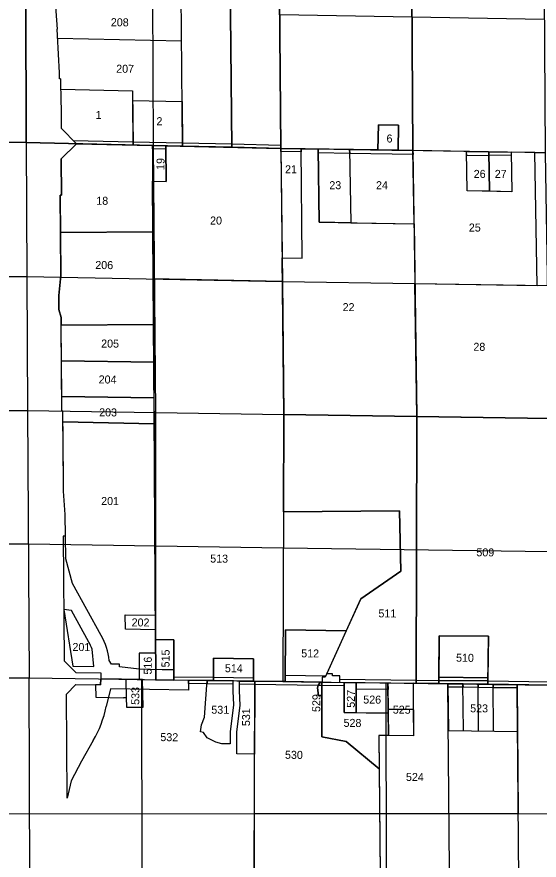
# Model space of a CAD drawing. Extents: x 582596 to 627039, y 145946 to 197316.
# Drawn here: x 594033 to 599237, y 163252 to 171651 of the extents above; entities that cross this region are included whole.
import ezdxf

# ---------------------------------------------------------------- set-up
doc = ezdxf.new("R2010")
doc.units = 0
for name, color, linetype in [('Defpoints 2', 7, 'Continuous'), ('E_RW_Existing', 7, 'Continuous'), ('E_RW_SixteenthLine', 7, 'Continuous'), ('P_RW_PropertyLine', 7, 'Continuous'), ('P_RW_QuarterLine', 7, 'Continuous'), ('P_RW_SectionLine', 7, 'Continuous')]:
    doc.layers.add(name, color=color, linetype=linetype)

msp = doc.modelspace()

# ---------------------------------------------------------------- linework, layer by layer
at = {"layer": 'Defpoints'}
msp.add_line((594439.8, 171440.4), (595673.8, 171412.6), dxfattribs=at)
msp.add_lwpolyline([(595191.7, 170375), (595187.7, 170818.2), (595679.3, 170807.1), (595683.3, 170363.9), (595191.7, 170375)], dxfattribs=at)
at = {"layer": 'E_RW_Existing'}
for p, q in [((594397.8, 172047.5), (594434, 171527.1)), ((594474.4, 168571.6), (594474.3, 168580.4)), ((594481.1, 167725.8), (594474.4, 168571.6)), ((594491.1, 167725.6), (594481.1, 167725.8)), ((594493.4, 167426.7), (594491.1, 167725.6)), ((594496.6, 167026.7), (594493.4, 167426.7)), ((594497.4, 166926.7), (594496.6, 167026.7)), ((594513.3, 166695.2), (594497.4, 166926.7)), ((594517.2, 166478.1), (594513.3, 166695.2)), ((594517.2, 166478.1), (594495, 166478.6)), ((594495, 166478.6), (594504.9, 165237)), ((594521.3, 166252.8), (594517.2, 166478.1)), ((594588.3, 166008.9), (594521.3, 166252.8)), ((594873.9, 165490.7), (594588.3, 166008.9)), ((594504.9, 165237), (594620.7, 165120.3)), ((594975, 165205.1), (594953.1, 165240.7)), ((595057.5, 165203.9), (594975, 165205.1)), ((595057.1, 165176.9), (595057.5, 165203.9)), ((595253.2, 165154), (595057.1, 165176.9)), ((595481.3, 165147.7), (595253.2, 165154)), ((595598.3, 165146), (595481.3, 165147.7)), ((595598.3, 165046), (595598.3, 165146)), ((594620.7, 165120.3), (594869.6, 165116.7)), ((594868.2, 165056.7), (595598.3, 165046)), ((594869.6, 165116.7), (594868.7, 165056.7))]:
    msp.add_line(p, q, dxfattribs=at)
for points in [[(594595.4, 170421.5), (595191.4, 170408), (595191.7, 170375), (594628.7, 170387.7)], [(595191.4, 170408), (595683, 170396.9), (595683.3, 170363.9), (595191.7, 170375)], [(595518.5, 170367.6), (595518.7, 170334.6), (595383.7, 170337.7), (595383.5, 170370.7)], [(596173.7, 170385.9), (596174, 170352.8), (595683.3, 170363.9), (595683, 170396.9)], [(596664.4, 170341.8), (596174, 170352.8), (596173.7, 170385.9), (596664.1, 170374.8)], [(596864.4, 170338.4), (596864.8, 170305.4), (596664.8, 170308.8), (596664.4, 170341.8)], [(597033.7, 170335.6), (597349.1, 170330.3), (597349.7, 170290.3), (597034.2, 170295.6)], [(597349.7, 170290.3), (597349.1, 170330.3), (597980, 170319.8), (597980.6, 170279.8)], [(598514.6, 170310.8), (598736, 170307.1), (598736.7, 170267.1), (598515.3, 170270.8)], [(598736, 170307.1), (598957.4, 170303.4), (598958, 170270.4), (598736.6, 170274.1)], [(595991.5, 165073.2), (595991.4, 165040.2), (595598.3, 165046), (595598.3, 165079)], [(595742.8, 165010.9), (595742.4, 165043.9), (595930.5, 165041.1), (595928.1, 165008.2)], [(596391.3, 165034.4), (595991.4, 165040.2), (595991.5, 165073.2), (596391.4, 165067.4)], [(596708.2, 165094.8), (597111.7, 165089.5), (597105, 165074.6), (597076.4, 165075), (597075.7, 165025), (596707.9, 165029.8)], [(597250.6, 165022.7), (597251.1, 165055.7), (598011.3, 165045.9), (598011.2, 165012.9)], [(598236.5, 165042.9), (598236.1, 165010), (598011.2, 165012.9), (598011.3, 165045.9)], [(598726.5, 165036.6), (598726.1, 165003.6), (598236.1, 165010), (598236.5, 165042.9)], [(598726.9, 165068.6), (598726.5, 165036.6), (598236.5, 165042.9), (598237, 165074.9)], [(595930.5, 165041.1), (596186.7, 165037.4), (596186.6, 165004.4), (595928.1, 165008.2)], [(596404.6, 165034.2), (596404.6, 165001.2), (596252.6, 165003.4), (596252.7, 165036.4)], [(596404.6, 165001.2), (596404.6, 165034.2), (596681.8, 165030.1), (597056.7, 165025.3), (597035.1, 164992.5)], [(597072.8, 165025), (597072.8, 164992), (597035.1, 164992.5), (597056.7, 165025.3)], [(597295.6, 165022.2), (597295.5, 164989.2), (597072.8, 164992), (597072.8, 165025)], [(597413.2, 164955.6), (597413.4, 165020.6), (597730.7, 165016.5), (597731.3, 164951.5)], [(598328.5, 164975.8), (598328.2, 165008.8), (598478.2, 165006.8), (598478.5, 164973.8)], [(598478.5, 164973.8), (598478.2, 165006.8), (598628.2, 165004.9), (598628.5, 164971.9)], [(598628.5, 164971.9), (598628.2, 165004.9), (598778.2, 165002.9), (598778.5, 164969.9)], [(599788.1, 165022.8), (599787.6, 164989.8), (599340.6, 164995.6), (598726.1, 165003.6), (598726.5, 165036.6), (599341.2, 165028.6)], [(598778.5, 164969.9), (598778.2, 165002.9), (599017.9, 164999.8), (599018.2, 164966.8)]]:
    msp.add_lwpolyline(points, close=True, dxfattribs=at)
msp.add_lwpolyline([(594794.5, 164442.2), (594676.6, 164237.3), (594574.6, 164043.6), (594535.8, 163868.7), (594527.5, 164906.8), (594621.6, 165000.3), (594867.9, 164996.7), (594868.8, 165056.7), (595742.4, 165043.9), (595743.8, 164945.8), (594964.9, 164957.3), (594924.3, 164781.8)], dxfattribs=at)
for centre, radius, start, end in [((594274.8, 165163.4), 682.7, 6.50215, 28.64904), ((593784.6, 165023), 1165, 330.10094, 348.05303)]:
    msp.add_arc(centre, radius, start, end, dxfattribs=at)
at = {"layer": 'E_RW_SixteenthLine'}
for p, q in [((595395.6, 170370.4), (595380.5, 173021.2)), ((597961, 172974.2), (597980, 170319.8)), ((599288.6, 171623.9), (596652.4, 171670.1)), ((595416.4, 167710.5), (595395.6, 170370.4)), ((597980, 170319.8), (598016.8, 167670.6)), ((591490.3, 169075.1), (594133.7, 169065.2)), ((594133.7, 169065.2), (596678.4, 169015.7)), ((596678.4, 169015.7), (599318.5, 168974.7)), ((595418.3, 165048.6), (595416.4, 167710.5)), ((598016.8, 167670.6), (598011.2, 165012.9)), ((594147.7, 166399.3), (591503.8, 166402.7)), ((596687.1, 166359.8), (594147.7, 166399.3)), ((599341, 166323.6), (596687.1, 166359.8)), ((595281.4, 162380), (595279.8, 165050.7)), ((597719.3, 162417.8), (597711.3, 165017)), ((591502, 163742), (594160.2, 163713)), ((594160.2, 163713), (596401, 163717.7)), ((596401, 163717.7), (599029.5, 163717.1)), ((599029.5, 163717.1), (601684.2, 163696.7))]:
    msp.add_line(p, q, dxfattribs=at)
at = {"layer": 'P_RW_PropertyLine'}
for p, q in [((594126.8, 170399), (594120.8, 173044)), ((594469.8, 171032.9), (594459.8, 171032.5)), ((594126.8, 170399), (596664.4, 170341.8)), ((594628.7, 170387.7), (594476.2, 170237.4)), ((595383.5, 170370.7), (595390, 170370.5)), ((595518.5, 170367.6), (595520.8, 170012)), ((596664.4, 170341.8), (596864.4, 170338.4)), ((599195.6, 170299.4), (599295.6, 170297.8)), ((594476.2, 170237.4), (594479, 169876.7)), ((595391, 170014.9), (595385.8, 170015)), ((595385.8, 170015), (595520.8, 170012)), ((594479, 169876.7), (594464, 169876.6)), ((594464, 169876.6), (594470.4, 169076.6)), ((594470.4, 169076.6), (594450.6, 168876.4)), ((594450.6, 168876.4), (594451.7, 168736.4)), ((594451.7, 168736.4), (594473.7, 168656.6)), ((594473.7, 168656.6), (594474.3, 168580.4)), ((594474.3, 168580.4), (595395, 168587.3)), ((595401.3, 167597.4), (595417.7, 165048.7)), ((594500.8, 165749.4), (594503, 165749.4)), ((595119.8, 165053), (595124, 164873.2)), ((595742.8, 165010.9), (595742.4, 165043.9)), ((598482.4, 164541.8), (598478.2, 165006.8)), ((598632.4, 164539.9), (598628.2, 165004.9)), ((598782.4, 164537.9), (598778.2, 165002.9))]:
    msp.add_line(p, q, dxfattribs=at)
for points in [[(596149.9, 173007.2), (596174, 170352.8), (595683.3, 170363.9), (595659.1, 173016.1), (596149.9, 173007.2)], [(596640.3, 172998.3), (596664.4, 170341.8), (596174, 170352.8), (596149.9, 173007.2), (596640.3, 172998.3)], [(594472.9, 170931.3), (595186.8, 170915.2), (595191.7, 170375), (594629, 170387.7)], [(594628.7, 170387.7), (594478.8, 170539.7), (594477.9, 170652.7)], [(597980, 170319.8), (597998.4, 168995.2), (599218.6, 168976.3), (599195.6, 170299.4), (598957.4, 170303.4), (598964.3, 169910.1), (598521.4, 169917.5), (598514.6, 170310.8), (597980, 170319.8)], [(596682, 165030.1), (596391.3, 165034.4), (596392.2, 165258.6), (595992.2, 165264.5), (595991.4, 165040.2), (595598.3, 165046), (595598, 165446), (595415.1, 165448.7), (595400.5, 167710.7), (595392.1, 169040.7), (596678.4, 169015.7), (596692.3, 167689.6), (596688.5, 166720.6), (597846.4, 166732.4), (597858.5, 166129.5), (597459.3, 165854.1), (597315.1, 165536.9), (596709.9, 165544.8), (596707.9, 165029.8), (596682, 165030.1)], [(594491.9, 167619.4), (595401.3, 167597.4), (595416, 165312.7), (595253.2, 165315.1), (595253.3, 165154), (595057.1, 165176.9), (595057.5, 165203.9), (594975, 165205.1), (594953.1, 165240.7)], [(594873.9, 165490.7), (594588.3, 166008.9), (594521.3, 166252.8), (594517.2, 166478.1), (594513.3, 166695.2), (594497.4, 166926.7), (594493.4, 167426.7), (594491.9, 167619.4)], [(594751.3, 165423.1), (594577.3, 165738.9), (594503, 165749.4), (594592.1, 165184.7), (594800.1, 165181.7)], [(594800.1, 165181.7), (594783.2, 165353.8)], [(596391.3, 165034.4), (595991.4, 165040.2), (595992.2, 165264.5), (596392.2, 165258.6), (596391.3, 165034.4)], [(596186.7, 165037.4), (596186.3, 164936.4), (596190.8, 164798.4), (596158.4, 164530.8), (596158, 164410.1), (596074.1, 164410.7), (596015.2, 164426.6), (595928.4, 164469.4), (595893.6, 164524.2), (595863.3, 164530.6), (595873.6, 164598.8), (595904.1, 164677.6), (595930.5, 165041.1), (596186.7, 165037.4)], [(597035.3, 164892.5), (597035.5, 164918.7), (597029.1, 164967.8), (597034.9, 164992.3), (597056.7, 165025.3)], [(597056.7, 165025.3), (597072.8, 165025), (597073, 164892), (597035.3, 164892.5)]]:
    msp.add_lwpolyline(points, dxfattribs=at)
for points in [[(596640.3, 172998.3), (597961, 172974.2), (597980, 170319.8), (597830.8, 170322.3), (597835, 170572.2), (597635, 170575.6), (597630.8, 170325.6), (596664.4, 170341.8)], [(597961, 172974.2), (599281.7, 172950), (599295.6, 170297.8), (597980, 170319.8)], [(597630.8, 170325.6), (597635, 170575.6), (597835, 170572.2), (597830.8, 170322.3)], [(594628.7, 170387.7), (595383.5, 170370.7), (595385.8, 170015), (595389.1, 169511.4), (594467, 169504.5), (594464, 169876.6), (594479, 169876.7), (594476.2, 170237.4)], [(596664.4, 170341.8), (596678.4, 169015.7), (595392.1, 169040.7), (595385.8, 170015), (595520.8, 170012), (595518.5, 170367.6)], [(597990.2, 169589.2), (598016.8, 167670.6), (596692.3, 167689.6), (596675.9, 169252.8), (596875.9, 169249.5), (596864.4, 170338.4), (597033.7, 170335.6), (597043.9, 169605)], [(597349.1, 170330.3), (597359.3, 169599.8), (597043.9, 169605), (597033.7, 170335.6)], [(597990.2, 169589.2), (597980, 170319.8), (597349.1, 170330.3), (597359.3, 169599.8)], [(599295.6, 170297.8), (599341.4, 167651.7), (598016.8, 167670.6), (597998.5, 168995.3), (599218.6, 168976.3), (599195.6, 170299.4)], [(598736, 170307.1), (598742.9, 169913.8), (598521.4, 169917.5), (598514.6, 170310.8)], [(598957.4, 170303.4), (598964.3, 169910.1), (598742.9, 169913.8), (598736, 170307.1)], [(594467, 169504.5), (595389.1, 169511.4), (595395, 168587.3), (594474.3, 168580.4), (594473.7, 168656.6), (594451.7, 168736.4), (594450.6, 168876.4), (594470.4, 169076.6)], [(594474.3, 168580.4), (595394.9, 168587.3), (595397.3, 168212.2), (594477.1, 168225.4)], [(594477.1, 168225.4), (595397.3, 168212.2), (595399.6, 167857.2), (594479.9, 167870.5)], [(594479.9, 167870.5), (595399.6, 167857.2), (595401.3, 167597.4), (594491.9, 167619.4), (594491.1, 167725.6), (594481.1, 167725.6)], [(596688.5, 166720.6), (596692.3, 167689.6), (598016.8, 167670.6), (598011.2, 165012.9), (597250.6, 165022.7), (597251.5, 165087.7), (597176.5, 165088.7), (597176.7, 165108.7), (597120.8, 165109.4), (597459.3, 165854.1), (597858.5, 166129.5), (597846.4, 166732.4)], [(599341.4, 167651.7), (600399.3, 167633), (600406.1, 164981.8), (600277.6, 164983.4), (600283.8, 165461.4), (599793.8, 165467.8), (599787.6, 164989.8), (599340.6, 164995.6), (598726.1, 165003.6), (598732.3, 165481.6), (598242.3, 165487.9), (598236.1, 165010), (598011.2, 165012.9), (598016.8, 167670.6)], [(599341.4, 167651.7), (599340.6, 164995.6), (598726.1, 165003.6), (598732.3, 165481.6), (598242.3, 165487.9), (598236.1, 165010), (598011.2, 165012.9), (598016.8, 167670.6)], [(595414.5, 165546.7), (595114.5, 165551.1), (595113.6, 165696.3), (595413.6, 165691.9)], [(596707.9, 165029.8), (596709.9, 165544.8), (597315.1, 165536.9), (597105, 165074.6), (597076.4, 165075), (597075.7, 165025)], [(598237, 165074.9), (598242.3, 165487.9), (598732.3, 165481.6), (598726.9, 165068.6)], [(595598.3, 165146), (595417.1, 165149.5), (595415.1, 165448.7), (595598, 165446)], [(595418.3, 165048.6), (595418.1, 165448.6), (595598, 165446), (595598.3, 165046)], [(595418.3, 165048.6), (595418.2, 165312.6), (595253.2, 165315.1), (595253.4, 165051.1)], [(594816.3, 164997.5), (594819.2, 164874.4), (595095.7, 164870.3), (595095.7, 164873.6), (595124, 164873.2), (595126.3, 164777.4), (595291.3, 164775), (595284.8, 165050.6), (594868.8, 165056.7), (594867.9, 164996.7)], [(596404.6, 165034.2), (596402.6, 164307.2), (596223.6, 164309.8), (596224.4, 164526.7), (596256.9, 164795.5), (596252.3, 164937.3), (596252.7, 165036.4)], [(597056.7, 165025.3), (597034.9, 164992.3), (597029.1, 164967.8), (597035.5, 164918.7), (597035.3, 164892.5), (597073, 164892), (597073.5, 164480.9), (597315.4, 164433.2), (597642.9, 164162), (597658.7, 162417.1), (596397.3, 162401.2), (596404.6, 165034.2), (596681.8, 165030.1)], [(597072.8, 165025), (597295.6, 165022.2), (597294.7, 164722.1), (597733.4, 164716.5), (597735.4, 164492.5), (597639.8, 164493.7), (597642.9, 164162), (597315.4, 164433.2), (597073.5, 164480.9)], [(597295.6, 165022.2), (597413.4, 165020.6), (597412.5, 164720.6), (597294.7, 164722.1)], [(597413.4, 165020.6), (597730.7, 165016.5), (597733.4, 164716.5), (597412.5, 164720.6)], [(598328.2, 165008.8), (597980.7, 165013.3), (597985.4, 164489.3), (597639.9, 164493.7), (597658.7, 162417.1), (598351.6, 162425.8)], [(597980.7, 165013.3), (597983.1, 164751.3), (597733.1, 164754.5), (597730.7, 165016.5)], [(599017.9, 164999.8), (598328.2, 165008.8), (598332.4, 164543.8), (599022.1, 164534.8)], [(599017.9, 164999.8), (599029.5, 163717.1), (600356.9, 163706.9), (600345.1, 164982.6), (599340.6, 164995.6)], [(597983.1, 164751.3), (597985.4, 164489.3), (597735.4, 164492.5), (597733.1, 164754.5)]]:
    msp.add_lwpolyline(points, close=True, dxfattribs=at)
for centre, radius, start, end in [((580243.9, 170539.9), 14224.5, 1.98477, 3.97988), ((580244.5, 170539.9), 14233.9, 0.45404, 1.98479), ((580244.5, 170539.9), 14233.9, 1.57576, 1.98479), ((580244.5, 170539.9), 14233.9, 0.45404, 1.57576), ((594274.8, 165163.4), 682.7, 6.50215, 28.64904), ((594287.1, 165167.3), 530, 20.60801, 28.86052)]:
    msp.add_arc(centre, radius, start, end, dxfattribs=at)
at = {"layer": 'P_RW_QuarterLine'}
msp.add_line((597983.1, 164751.3), (597733.1, 164754.5), dxfattribs=at)
at = {"layer": 'P_RW_SectionLine'}
for p, q in [((594120.8, 173044), (594126.8, 170399)), ((596640.3, 172998.3), (596664.4, 170341.8)), ((594126.8, 170399), (591482.1, 170411.2)), ((596664.4, 170341.8), (594126.8, 170399)), ((594126.8, 170399), (594140.5, 167731.4)), ((599295.6, 170297.8), (596664.4, 170341.8)), ((596664.4, 170341.8), (596692.3, 167689.6)), ((591498.6, 167739.1), (594140.5, 167731.4)), ((594140.5, 167731.4), (596692.3, 167689.6)), ((594140.5, 167731.4), (594154.9, 165067.2)), ((596692.3, 167689.6), (596681.8, 165030.1)), ((596692.3, 167689.6), (599341.4, 167651.7)), ((591509.1, 165066.3), (594154.9, 165067.2)), ((594154.9, 165067.2), (596681.8, 165030.1)), ((594165.6, 162358.7), (594154.9, 165067.2)), ((596397.3, 162401.2), (596404.6, 165034.2)), ((596681.8, 165030.1), (599340.6, 164995.6)), ((599041.2, 162434.4), (599017.9, 164999.8))]:
    msp.add_line(p, q, dxfattribs=at)

# ---------------------------------------------------------------- texts
at = {"layer": 'Defpoints 2'}
for s, rotation, p in [('208', 359.50421, (594969.5, 171558.3)), ('207', 359.50421, (595022.8, 171095.1)), ('19', 88.56414, (595502.8, 170125.9)), ('18', 359.50421, (594824.4, 169780.4)), ('20', 359.50421, (595958.3, 169583.2)), ('206', 359.50421, (594814.7, 169140.1)), ('205', 359.50421, (594873, 168358.1)), ('204', 359.50421, (594848, 168000.4)), ('203', 359.50421, (594852.8, 167672.9)), ('201', 359.50421, (594872.8, 166790)), ('509', 359.50421, (598611.5, 166278.7)), ('513', 359.50652, (595959.6, 166216.3)), ('511', 359.50652, (597635.4, 165670.3)), ('202', 359.50652, (595176.7, 165580.7)), ('201', 359.50421, (594587, 165335.6)), ('515', 89.50652, (595553.8, 165171.6)), ('512', 359.50652, (596866.2, 165272.1)), ('510', 359.50652, (598408.9, 165228.6)), ('516', 89.50652, (595376.5, 165100.2)), ('514', 359.50652, (596105.7, 165124.1)), ('533', 89.50786, (595252.8, 164798.5)), ('529', 89.50652, (597056.2, 164727.4)), ('527', 89.50652, (597400.5, 164769.8)), ('526', 359.50652, (597484.4, 164812.1)), ('531', 359.50786, (595970.6, 164710.8)), ('525', 359.50652, (597778.6, 164711.7)), ('523', 359.50652, (598549.6, 164724.9)), ('531', 89.50786, (596356.2, 164586.7)), ('528', 359.50652, (597288, 164580)), ('532', 359.50786, (595462.9, 164437.9)), ('530', 359.50652, (596704.6, 164261.9)), ('524', 359.50652, (597909.7, 164041.4))]:
    msp.add_text(s, height=79.68, rotation=rotation, dxfattribs=at).set_placement(p)
for s, height, p in [('1', 79.7, (594817.3, 170634.1)), ('2', 79.7, (595424, 170572.1)), ('6', 79.7, (597716.4, 170399.8)), ('21', 79.68, (596705.6, 170093.4)), ('26', 79.68, (598585.1, 170047.3)), ('27', 79.68, (598795.1, 170047.3)), ('23', 79.68, (597146.6, 169934.9)), ('24', 79.68, (597611.6, 169934.9)), ('25', 79.68, (598536.6, 169513.2)), ('22', 79.68, (597279.2, 168720.1)), ('28', 79.68, (598582, 168325.2))]:
    msp.add_text(s, height=height, dxfattribs=at).set_placement(p)

doc.saveas('drawing.dxf')
